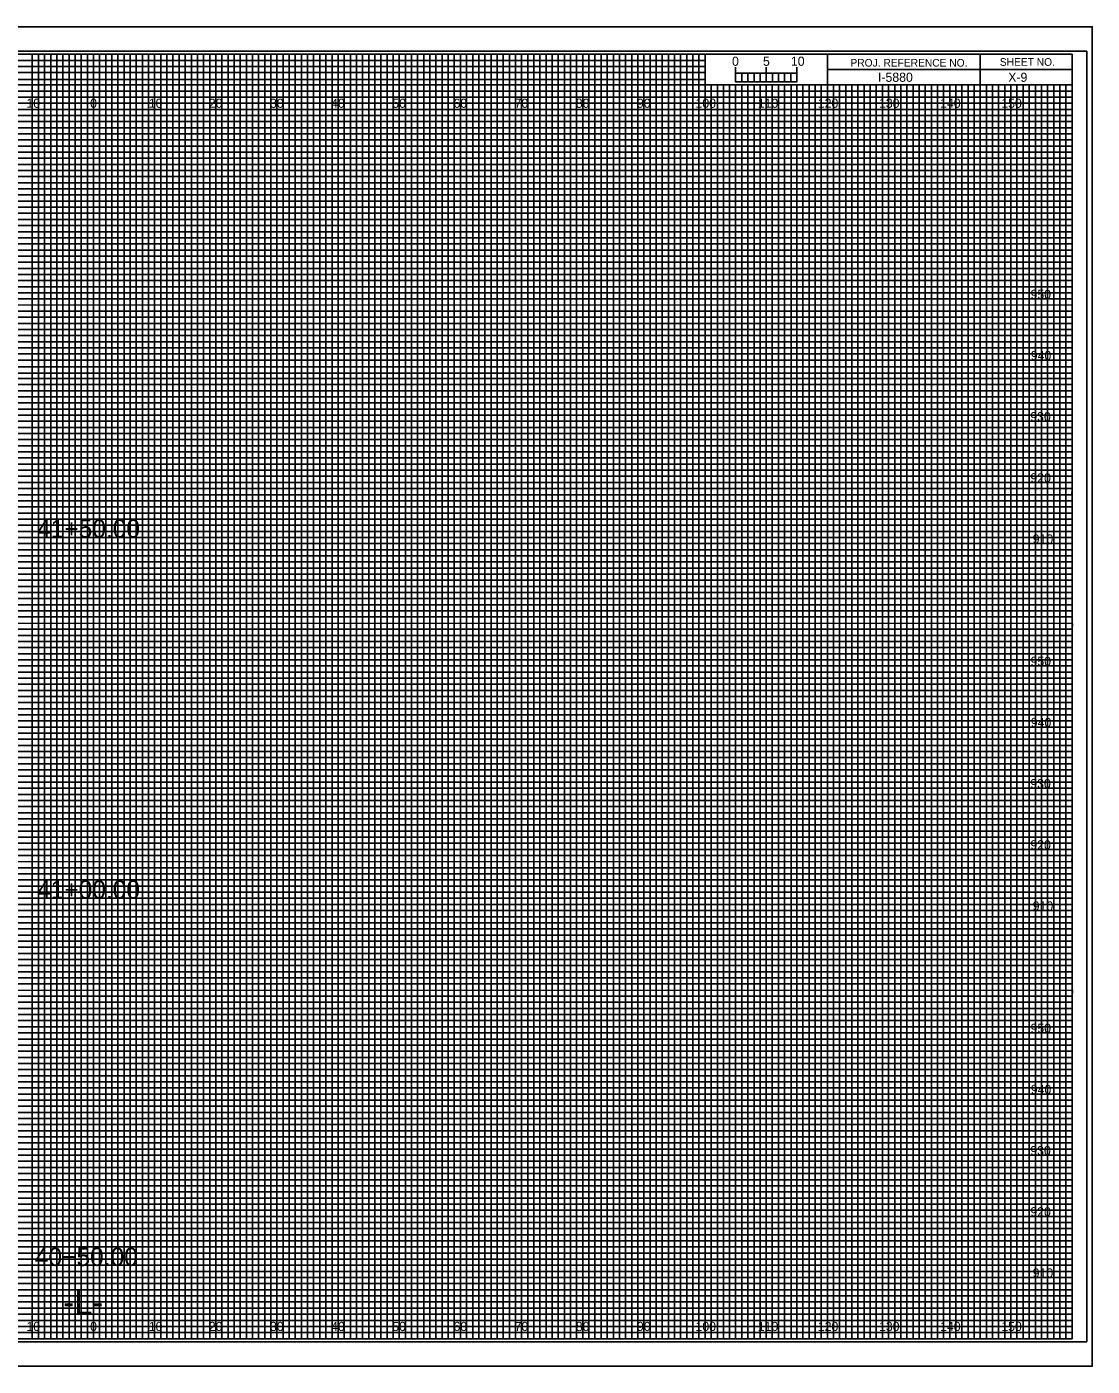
# Model space of a CAD drawing. Extents: x -13 to 323, y -4 to 3074.
# Drawn here: x 149.1 to 323.3, y 1535.5 to 1754.5 of the extents above; entities that cross this region are included whole.
import ezdxf

# ---------------------------------------------------------------- set-up
doc = ezdxf.new("R2010")
doc.units = 0
for name, color, linetype in [('Prop XS Alignment Label', 7, 'Continuous'), ('Prop XS Bar Scale Labels', 7, 'Continuous'), ('Prop XS Elevation Labels', 7, 'Continuous'), ('Prop XS Offset Labels', 7, 'Continuous'), ('Prop XS Project Number', 7, 'Continuous'), ('Prop XS Sheet Number', 7, 'Continuous'), ('Prop XS Station Labels', 7, 'Continuous'), ('Sheet Cross Section CELL', 7, 'Continuous'), ('Sheet Cross Section Grid Major CELL', 7, 'Continuous'), ('Sheet Cross Section Grid Middle CELL', 7, 'Continuous'), ('Sheet Cross Section Grid Minor 1 CELL', 7, 'Continuous'), ('Sheet Cross Section Grid Minor 2 CELL', 7, 'Continuous'), ('Sheet Cross Section Scale CELL', 7, 'Continuous'), ('Sheet Cutting Line CELL', 7, 'Continuous'), ('Sheet DOT Grid CELL', 7, 'Continuous'), ('Sheet Plot Border Inside CELL', 7, 'Continuous'), ('Sheet Plot Border Outside CELL', 7, 'Continuous')]:
    doc.layers.add(name, color=color, linetype=linetype)

msp = doc.modelspace()

# ---------------------------------------------------------------- linework, layer by layer
at = {"layer": 'Sheet Cross Section CELL'}
for p, q in [((305, 1750), (305, 1745)), ((305, 1745), (305, 1750)), ((280, 1747.5), (280, 1745)), ((320, 1747.49), (280, 1747.49)), ((280, 1745), (320, 1745))]:
    msp.add_line(p, q, dxfattribs=at)
for points in [[(320, 1750), (0, 1750), (0, 1540), (320, 1540)], [(280, 1750), (260, 1750), (260, 1745.03), (280, 1745.03)], [(320, 1750), (280, 1750), (280, 1745), (320, 1745)]]:
    msp.add_lwpolyline(points, close=True, dxfattribs=at)
at = {"layer": 'Sheet Cross Section Grid Major CELL'}
for p, q in [((150, 1750), (140, 1750)), ((150, 1540), (150, 1750)), ((170, 1750), (160, 1750)), ((160, 1750), (160, 1540)), ((170, 1540), (170, 1750)), ((190, 1750), (180, 1750)), ((180, 1750), (180, 1540)), ((190, 1540), (190, 1750)), ((210, 1750), (200, 1750)), ((200, 1750), (200, 1540)), ((210, 1540), (210, 1750)), ((230, 1750), (220, 1750)), ((220, 1750), (220, 1540)), ((230, 1540), (230, 1750)), ((250, 1750), (240, 1750)), ((240, 1750), (240, 1540)), ((250, 1540), (250, 1750)), ((260, 1750), (260, 1540)), ((270, 1540), (270, 1745)), ((290, 1745), (280, 1745)), ((280, 1745), (280, 1540)), ((290, 1540), (290, 1745)), ((310, 1745), (300, 1745)), ((300, 1745), (300, 1540)), ((310, 1540), (310, 1745)), ((160, 1540), (150, 1540)), ((180, 1540), (170, 1540)), ((200, 1540), (190, 1540)), ((220, 1540), (210, 1540)), ((240, 1540), (230, 1540)), ((260, 1540), (250, 1540)), ((280, 1540), (270, 1540)), ((300, 1540), (290, 1540)), ((320, 1540), (310, 1540)), ((320, 1540), (320, 1540))]:
    msp.add_line(p, q, dxfattribs=at)
for points in [[(0, 1740), (320, 1740), (320, 1730), (0, 1730)], [(0, 1720), (320, 1720), (320, 1710), (0, 1710)], [(0, 1700), (320, 1700), (320, 1690), (0, 1690)], [(0, 1680), (320, 1680), (320, 1670), (0, 1670)], [(0, 1660), (320, 1660), (320, 1650), (0, 1650)], [(0, 1640), (320, 1640), (320, 1630), (0, 1630)], [(0, 1620), (320, 1620), (320, 1610), (0, 1610)], [(0, 1600), (320, 1600), (320, 1590), (0, 1590)], [(0, 1580), (320, 1580), (320, 1570), (0, 1570)], [(0, 1560), (320, 1560), (320, 1550), (0, 1550)]]:
    msp.add_lwpolyline(points, dxfattribs=at)
at = {"layer": 'Sheet Cross Section Grid Middle CELL'}
for points in [[(145, 1540), (155, 1540), (155, 1750), (165, 1750), (165, 1540), (175, 1540), (175, 1750), (185, 1750), (185, 1540), (195, 1540), (195, 1750), (205, 1750), (205, 1540), (215, 1540), (215, 1750), (225, 1750), (225, 1540), (235, 1540), (235, 1750), (245, 1750), (245, 1540), (255, 1540), (255, 1750), (259.93, 1750), (260, 1750), (260, 1745), (264.99, 1745), (264.99, 1540), (275, 1540), (275, 1745), (285, 1745), (285, 1540), (295, 1540), (295, 1745), (305, 1745), (305, 1540), (315, 1540), (315, 1745)], [(0, 1745), (275, 1745)], [(0, 1725), (320, 1725), (320, 1735), (0, 1735)], [(0, 1705), (320, 1705), (320, 1715), (0, 1715)], [(0, 1685), (320, 1685), (320, 1695), (0, 1695)], [(0, 1665), (320, 1665), (320, 1675), (0, 1675)], [(0, 1645), (320, 1645), (320, 1655), (0, 1655)], [(0, 1625), (320, 1625), (320, 1635), (0, 1635)], [(0, 1605), (320, 1605), (320, 1615), (0, 1615)], [(0, 1585), (320, 1585), (320, 1595), (0, 1595)], [(0, 1565), (320, 1565), (320, 1575), (0, 1575)], [(0, 1545), (320, 1545), (320, 1555), (0, 1555)]]:
    msp.add_lwpolyline(points, dxfattribs=at)
at = {"layer": 'Sheet Cross Section Grid Minor 1 CELL'}
for p, q in [((0, 1749), (260, 1749)), ((260, 1747.98), (0, 1747.98)), ((260, 1749), (260, 1747.98)), ((0, 1747), (260, 1747)), ((260, 1745.89), (0, 1745.89)), ((260, 1747), (260, 1745.89)), ((0, 1744), (320, 1744))]:
    msp.add_line(p, q, dxfattribs=at)
for points in [[(0, 1743), (270, 1743), (320, 1743), (320, 1742), (0, 1742)], [(0, 1741), (320, 1741), (320, 1739), (0, 1739)], [(0, 1738), (320, 1738), (320, 1737), (0, 1736.98)], [(0, 1736), (320, 1736), (320, 1734), (0, 1734)], [(0, 1733), (320, 1733), (320, 1732), (0, 1732)], [(0, 1731), (320, 1731), (320, 1729), (0, 1729)], [(0, 1728), (320, 1728), (320, 1727), (0, 1727)], [(0, 1726), (320, 1726), (320, 1724), (0, 1724)], [(0, 1723), (320, 1723), (320, 1722), (0, 1722)], [(0, 1721), (320, 1721), (320, 1719), (0, 1719)], [(0, 1718), (320, 1718), (320, 1717), (0, 1717)], [(0, 1716), (320, 1716), (320, 1713.95), (320, 1713), (320, 1712), (0, 1712)], [(0, 1714), (320, 1714), (320, 1713), (0, 1713)], [(0, 1711), (320, 1711), (320, 1709), (0, 1709.03)], [(0, 1709.03), (320, 1709), (320, 1708), (0, 1708)], [(0, 1707), (320, 1707), (320, 1706), (0, 1706)], [(0, 1704), (320, 1704), (320, 1703), (0, 1703)], [(0, 1702), (320, 1702), (320, 1701), (0, 1701)], [(-0.07, 1698.89), (320, 1698.89), (320, 1697.88), (-0.07, 1697.88)], [(0, 1697), (320, 1697), (320, 1696), (0, 1696)], [(0, 1694), (320, 1694), (320, 1693), (0, 1693)], [(0, 1692), (320, 1692), (320, 1691), (0, 1691)], [(0, 1689), (320, 1689), (320, 1688), (0, 1688)], [(0, 1687), (320, 1687), (320, 1686), (0, 1686)], [(0, 1684), (320, 1684), (320, 1683), (0, 1683)], [(0, 1682), (320, 1682), (320, 1681), (0, 1681)], [(0, 1679), (320, 1679), (319.99, 1677.98), (0, 1678)], [(0, 1677), (320, 1677), (320, 1676), (0, 1676)], [(0, 1674), (320, 1674), (320, 1673), (0, 1673)], [(0, 1672), (320, 1672), (320, 1671), (0, 1671)], [(0, 1669), (320, 1669), (320, 1668), (0, 1668)], [(0, 1667), (320, 1667), (320, 1666), (0, 1666)], [(0, 1664), (320, 1664), (320, 1663), (0, 1663)], [(0, 1662), (320, 1662), (320, 1661), (0, 1661)], [(0, 1659), (320, 1659), (320, 1658), (0, 1658)], [(0, 1656.99), (320.07, 1656.91), (320, 1656), (0, 1656)], [(0, 1654), (320, 1654), (320, 1653), (0, 1653)], [(0, 1652), (320, 1652), (320, 1651), (0, 1651)], [(0, 1649), (320, 1649), (320, 1648), (0, 1648)], [(0, 1647), (320, 1647), (320, 1646), (0, 1646)], [(0, 1644), (320, 1644), (320, 1643), (0, 1643)], [(0, 1642), (320, 1642), (320, 1641), (0, 1641)], [(0, 1639), (320, 1639), (320, 1638), (0, 1638)], [(0, 1637), (320, 1637), (320, 1636), (0, 1636)], [(0, 1634), (320, 1634), (320, 1633), (0, 1633)], [(0, 1632), (320, 1632), (320, 1631), (0, 1631)], [(0, 1629), (320, 1629), (320, 1628), (0, 1628)], [(0, 1627), (320, 1627), (320, 1626), (0, 1626)], [(0, 1624), (320, 1624), (320, 1623), (0, 1623)], [(0, 1622), (320, 1622), (320, 1621), (0, 1621)], [(0, 1619), (320, 1619), (319.99, 1617.98), (0, 1618)], [(0, 1617), (320, 1617), (320, 1616), (0, 1616)], [(0, 1614), (320, 1614), (320, 1613), (0, 1613)], [(0, 1612), (320, 1612), (320, 1611), (0, 1611)], [(0, 1609), (320, 1609), (320, 1608), (0, 1608)], [(0, 1607), (320, 1607), (320, 1606), (0, 1606)], [(0, 1604), (320, 1604), (320, 1603), (0, 1603)], [(0, 1602), (320, 1602), (320, 1601), (0, 1601)], [(0, 1599), (320, 1599), (320, 1598), (0, 1598)], [(0, 1596.99), (320.07, 1596.91), (320, 1596), (0, 1596)], [(0, 1594), (320, 1594), (320, 1593), (0, 1593)], [(0, 1592), (320, 1592), (320, 1591), (0, 1591)], [(0, 1589), (320, 1589), (320, 1588), (0, 1588)], [(0, 1587), (320, 1587), (320, 1586), (0, 1586)], [(0, 1584), (320, 1584), (320, 1583), (0, 1583)], [(0, 1582), (320, 1582), (320, 1581), (0, 1581)], [(0, 1579), (320, 1579), (320, 1578), (0, 1578)], [(0, 1577), (320, 1577), (320, 1576), (0, 1576)], [(0, 1574), (320, 1574), (320, 1573), (0, 1573)], [(0, 1572), (320, 1572), (320, 1571), (0, 1571)], [(0, 1569), (320, 1569), (320, 1568), (0, 1568)], [(0, 1567), (320, 1567), (320, 1566), (0, 1566)], [(0, 1564), (320, 1564), (320, 1563), (0, 1563)], [(0, 1562), (320, 1562), (320, 1561), (0, 1561)], [(0, 1559), (320, 1559), (320, 1558), (0, 1558)], [(0, 1557), (320, 1557), (320, 1556), (0, 1556)], [(0, 1554), (320, 1554), (320, 1553), (0, 1553)], [(0, 1552), (320, 1552), (320, 1551), (0, 1551)], [(0, 1549), (320, 1549), (320, 1548), (0, 1548)], [(0, 1547), (320, 1547), (320, 1546), (0, 1546)], [(0, 1544), (320, 1544), (320, 1543), (0, 1543)], [(0, 1542), (320, 1542), (320, 1541), (0, 1541)]]:
    msp.add_lwpolyline(points, dxfattribs=at)
at = {"layer": 'Sheet Cross Section Grid Minor 2 CELL'}
for p, q in [((267, 1745), (266.01, 1745)), ((266.01, 1745), (266.01, 1540)), ((267, 1540), (267, 1745)), ((269, 1745), (268, 1745)), ((268, 1745), (268, 1540)), ((269, 1540), (269, 1745)), ((266.01, 1540), (265, 1540)), ((268, 1540), (267, 1540))]:
    msp.add_line(p, q, dxfattribs=at)
for points in [[(150, 1540), (151, 1540), (151, 1750), (152, 1750), (152, 1540)], [(152, 1540), (153, 1540), (153, 1750), (154, 1750), (154, 1540)], [(155, 1540), (156, 1540), (156, 1750), (157, 1750), (157, 1540)], [(157, 1540), (158, 1540), (158, 1750), (159, 1750), (159, 1540)], [(160, 1540), (161, 1540), (161, 1750), (162, 1750), (162, 1540)], [(162, 1540), (163, 1540), (163, 1750), (164, 1750), (164, 1540)], [(165, 1540), (166, 1540), (166, 1750), (167, 1750), (167, 1540)], [(167, 1540), (168, 1540), (168, 1750), (169, 1750), (169, 1540)], [(170, 1540), (171, 1540), (171, 1750), (172, 1750), (172, 1540)], [(172, 1540), (173, 1540), (173, 1750), (174, 1750), (174, 1540)], [(175, 1540), (176, 1540), (176, 1750), (177, 1750), (177, 1540)], [(177, 1540), (178, 1540), (178, 1750), (179, 1750), (179, 1540)], [(180, 1540), (181, 1540), (181, 1750), (182, 1750), (182, 1540)], [(182, 1540), (183, 1540), (183, 1750), (184, 1750), (184, 1540)], [(185, 1540), (186, 1540), (186, 1750), (187, 1750), (187, 1540)], [(187, 1540), (188, 1540), (188, 1750), (189, 1750), (189, 1540)], [(190, 1540), (191, 1540), (191, 1750), (192, 1750), (192, 1540)], [(192, 1540), (193, 1540), (193, 1750), (194, 1750), (194, 1540)], [(195, 1540), (196, 1540), (196, 1750), (197, 1750), (197, 1540)], [(197, 1540), (198, 1540), (198, 1750), (199, 1750), (199, 1540)], [(200, 1540), (201, 1540), (201, 1750), (202, 1750), (202, 1540)], [(202, 1540), (203, 1540), (203, 1750), (204, 1750), (204, 1540)], [(205, 1540), (206, 1540), (206, 1750), (207, 1750), (207, 1540)], [(207, 1540), (208, 1540), (208, 1750), (209, 1750), (209, 1540)], [(210, 1540), (211, 1540), (211, 1750), (212, 1750), (212, 1540)], [(212, 1540), (213, 1540), (213, 1750), (214, 1750), (214, 1540)], [(215, 1540), (216, 1540), (216, 1750), (217, 1750), (217, 1540)], [(217, 1540), (218, 1540), (218, 1750), (219, 1750), (219, 1540)], [(220, 1540), (221, 1540), (221, 1750), (222, 1750), (222, 1540)], [(222, 1540), (223, 1540), (223, 1750), (224, 1750), (224, 1540)], [(225, 1540), (226, 1540), (226, 1750), (227, 1750), (227, 1540)], [(227, 1540), (228, 1540), (228, 1750), (229, 1750), (229, 1540)], [(230, 1540), (231, 1540), (231, 1750), (232, 1750), (232, 1540)], [(232, 1540), (233, 1540), (233, 1750), (234, 1750), (234, 1540)], [(235, 1540), (236, 1540), (236, 1750), (237, 1750), (237, 1540)], [(237, 1540), (238, 1540), (238, 1750), (239, 1750), (239, 1540)], [(240, 1540), (241, 1540), (241, 1750), (242, 1750), (242, 1540)], [(242, 1540), (243, 1540), (243, 1750), (244, 1750), (244, 1540)], [(245, 1540), (246, 1540), (246, 1750), (247, 1750), (247, 1540)], [(247, 1540), (248, 1540), (248, 1750), (249, 1750), (249, 1540)], [(250, 1540), (251, 1540), (251, 1750), (252, 1750), (252, 1540)], [(252, 1540), (253, 1540), (253, 1750), (254, 1750), (254, 1540)], [(255, 1540), (256, 1540), (256, 1750), (257, 1750), (257, 1540)], [(257, 1540), (258, 1540), (258, 1750), (259, 1750), (259, 1540)], [(260, 1540), (261, 1540), (261, 1745), (262.02, 1745), (262.02, 1540)], [(262, 1540), (263, 1540), (263, 1745), (263.99, 1745), (263.99, 1540)], [(270, 1540), (270.98, 1540), (270.98, 1745), (272, 1745), (272, 1540)], [(272, 1540), (273, 1540), (273, 1745), (274.05, 1745), (274.05, 1540)], [(275, 1540), (276, 1540), (276, 1745), (277, 1745), (277, 1540)], [(277, 1540), (278, 1540), (278, 1745), (279, 1745), (279, 1540)], [(280, 1540), (281, 1540), (281, 1745), (282, 1745), (282, 1540)], [(282, 1540), (283, 1540), (283, 1745), (284, 1745), (284, 1540)], [(285, 1540), (286, 1540), (286, 1745), (287, 1745), (287, 1540)], [(287, 1540), (288, 1540), (288, 1745), (289, 1745), (289, 1540)], [(290, 1540), (291, 1540), (291, 1745), (292, 1745), (292, 1540)], [(292, 1540), (293, 1540), (293, 1745), (294, 1745), (294, 1540)], [(295, 1540), (296, 1540), (296, 1745), (297, 1745), (297, 1540)], [(297, 1540), (298, 1540), (298, 1745), (299, 1745), (299, 1540)], [(300, 1540), (301, 1540), (301, 1745), (302, 1745), (302, 1540)], [(302, 1540), (303, 1540), (303, 1745), (304, 1745), (304, 1540)], [(305, 1540), (306, 1540), (306, 1745), (307, 1745), (307, 1540)], [(307, 1540), (308, 1540), (308, 1745), (309, 1745), (309, 1540)], [(310, 1540), (311, 1540), (311, 1745), (312, 1745), (312, 1540)], [(312, 1540), (313, 1540), (313, 1745), (314, 1745), (314, 1540)], [(315, 1540), (316, 1540), (316, 1745), (317, 1745), (317, 1540)], [(317, 1540), (318, 1540), (318, 1745), (319, 1745), (319, 1540)]]:
    msp.add_lwpolyline(points, dxfattribs=at)
at = {"layer": 'Sheet Cross Section Scale CELL'}
for p, q in [((265, 1745.49), (265, 1747.9)), ((265, 1746.9), (265, 1747.9)), ((270, 1745.49), (270, 1747.9)), ((275, 1745.49), (275, 1747.9)), ((275, 1746.9), (275, 1747.9))]:
    msp.add_line(p, q, dxfattribs=at)
for points in [[(275, 1746.9), (265, 1746.9), (265, 1745.49), (275, 1745.49)], [(265, 1746.9), (266, 1746.9), (266, 1745.49), (265, 1745.49)], [(267, 1746.9), (268, 1746.9), (268, 1745.49), (267, 1745.49)], [(269, 1746.9), (270, 1746.9), (270, 1745.49), (269, 1745.49)], [(271, 1746.9), (272, 1746.9), (272, 1745.49), (271, 1745.49)], [(273, 1746.9), (274, 1746.9), (274, 1745.49), (273, 1745.49)]]:
    msp.add_lwpolyline(points, close=True, dxfattribs=at)
at = {"layer": 'Sheet Cutting Line CELL'}
for p, q in [((323.3, 1754.5), (-13.4, 1754.5)), ((-13.4, 1535.5), (323.3, 1535.5))]:
    msp.add_line(p, q, dxfattribs=at)
at = {"layer": 'Sheet DOT Grid CELL'}
for p, q in [((150, 1540), (150, 1750)), ((160, 1540), (160, 1750)), ((170, 1540), (170, 1750)), ((180, 1540), (180, 1750)), ((190, 1540), (190, 1750)), ((200, 1540), (200, 1750)), ((210, 1540), (210, 1750)), ((220, 1540), (220, 1750)), ((230, 1540), (230, 1750)), ((240, 1540), (240, 1750)), ((250, 1540), (250, 1750)), ((260, 1540), (260, 1744.69)), ((270, 1540), (270, 1744.69)), ((280, 1540), (280, 1744.69)), ((290, 1540), (290, 1744.69)), ((300, 1540), (300, 1744.69)), ((310, 1540), (310, 1744.69)), ((0, 1740), (320, 1740)), ((0, 1730), (320, 1730)), ((0, 1720), (320, 1720)), ((0, 1710), (320, 1710)), ((0, 1700), (320, 1700)), ((0, 1690), (320, 1690)), ((0, 1680), (320, 1680)), ((0, 1670), (320, 1670)), ((0, 1660), (320, 1660)), ((0, 1650), (320, 1650)), ((0, 1640), (320, 1640)), ((0, 1630), (320, 1630)), ((0, 1620), (320, 1620)), ((0, 1610), (320, 1610)), ((0, 1600), (320, 1600)), ((0, 1590), (320, 1590)), ((0, 1580), (320, 1580)), ((0, 1570), (320, 1570)), ((0, 1560), (320, 1560)), ((0, 1550), (320, 1550))]:
    msp.add_line(p, q, dxfattribs=at)
at = {"layer": 'Sheet Plot Border Inside CELL'}
msp.add_lwpolyline([(-10.8, 1539.5), (322.4, 1539.5), (322.4, 1750.5), (-10.8, 1750.5)], close=True, dxfattribs=at)
at = {"layer": 'Sheet Plot Border Outside CELL'}
msp.add_lwpolyline([(-13.4, 1535.5), (323.3, 1535.5), (323.3, 1754.5), (-13.4, 1754.5)], close=True, dxfattribs=at)

# ---------------------------------------------------------------- texts
at = {"layer": 'Prop XS Alignment Label'}
msp.add_text('-L-', height=4, dxfattribs=at).set_placement((155.06, 1544))
at = {"layer": 'Prop XS Bar Scale Labels'}
for s, p in [('5', (269.47, 1748.12)), ('10', (274.04, 1748.12))]:
    msp.add_text(s, height=1.5, dxfattribs=at).set_placement(p)
at = {"layer": 'Prop XS Elevation Labels'}
for s, p in [('950', (313.22, 1710)), ('940', (313.26, 1700)), ('930', (313.18, 1690)), ('920', (313.19, 1680)), ('910', (313.57, 1670)), ('950', (313.22, 1650)), ('940', (313.26, 1640)), ('930', (313.18, 1630)), ('920', (313.19, 1620)), ('910', (313.57, 1610)), ('950', (313.22, 1590)), ('940', (313.26, 1580)), ('930', (313.18, 1570)), ('920', (313.19, 1560)), ('910', (313.57, 1550))]:
    msp.add_text(s, height=1.5, dxfattribs=at).set_placement(p)
at = {"layer": 'Prop XS Offset Labels'}
for s, p in [('10', (149.04, 1741.25)), ('0', (159.45, 1741.25)), ('0', (159.45, 1741.25)), ('10', (169.04, 1741.25)), ('20', (178.86, 1741.25)), ('30', (188.86, 1741.25)), ('40', (198.86, 1741.25)), ('50', (208.86, 1741.25)), ('60', (218.86, 1741.25)), ('70', (228.86, 1741.25)), ('80', (238.86, 1741.25)), ('90', (248.86, 1741.25)), ('100', (258.44, 1741.25)), ('110', (268.62, 1741.25)), ('120', (278.44, 1741.25)), ('130', (288.44, 1741.25)), ('140', (298.44, 1741.25)), ('150', (308.44, 1741.25)), ('10', (149.04, 1541.25)), ('0', (159.45, 1541.25)), ('0', (159.45, 1541.25)), ('10', (169.04, 1541.25)), ('20', (178.86, 1541.25)), ('30', (188.86, 1541.25)), ('40', (198.86, 1541.25)), ('50', (208.86, 1541.25)), ('60', (218.86, 1541.25)), ('70', (228.86, 1541.25)), ('80', (238.86, 1541.25)), ('90', (248.86, 1541.25)), ('100', (258.44, 1541.25)), ('110', (268.62, 1541.25)), ('120', (278.44, 1541.25)), ('130', (288.44, 1541.25)), ('140', (298.44, 1541.25)), ('150', (308.44, 1541.25))]:
    msp.add_text(s, height=1.5, dxfattribs=at).set_placement(p)
at = {"layer": 'Prop XS Project Number'}
msp.add_text('I-5880', height=1.5, dxfattribs=at).set_placement((288.28, 1745.5))
at = {"layer": 'Prop XS Sheet Number'}
msp.add_text('X-9', height=1.5, dxfattribs=at).set_placement((309.57, 1745.5))
at = {"layer": 'Prop XS Station Labels'}
for s, p in [('41+50.00', (150.77, 1670.95)), ('41+00.00', (150.77, 1611.94)), ('40+50.00', (150.41, 1551.89))]:
    msp.add_text(s, height=3, dxfattribs=at).set_placement(p)
at = {"layer": 'Sheet Cross Section CELL'}
for s, p in [('PROJ. REFERENCE NO.', (283.77, 1747.99)), ('SHEET NO.', (308.19, 1748.12))]:
    msp.add_text(s, height=1.25, dxfattribs=at).set_placement(p)
at = {"layer": 'Sheet Cross Section Scale CELL'}
msp.add_text('0', height=1.5, dxfattribs=at).set_placement((264.41, 1748.12))

doc.saveas('drawing.dxf')
